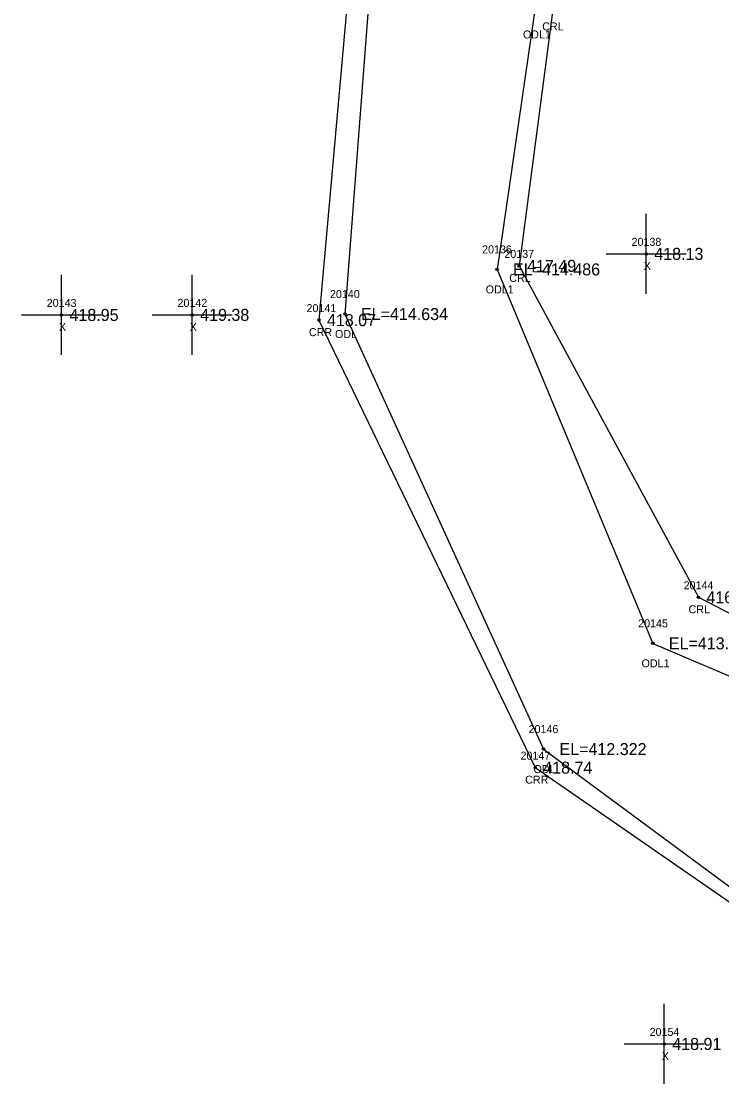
# Model space of a CAD drawing. Extents: x 1613184 to 1614731, y 770859 to 771868.
# Drawn here: x 1613872.1 to 1613959.6, y 771132.5 to 771266.5 of the extents above; entities that cross this region are included whole.
import ezdxf

# ---------------------------------------------------------------- set-up
doc = ezdxf.new("R2010")
doc.units = 0
for name, color, linetype in [('RD_EX_H2O', 7, 'Continuous'), ('RD_EX_H2O_txCode', 7, 'Continuous'), ('RD_EX_Misc', 7, 'Continuous'), ('RD_EX_Misc_txCode', 7, 'Continuous'), ('RD_EX_TX_H2O_ELEV', 7, 'Continuous'), ('RD_EX_TX_Misc_ELEV', 7, 'Continuous'), ('RD_SMD_Locator', 7, 'Continuous')]:
    doc.layers.add(name, color=color, linetype=linetype)

msp = doc.modelspace()

# ---------------------------------------------------------------- linework, layer by layer
at = {"layer": 'RD_EX_H2O'}
for points in [[(1613914.71, 771327.05), (1613912.94, 771270.2), (1613909.29, 771229.14), (1613936.32, 771173.24), (1613961.59, 771155.78), (1613976.99, 771153.11), (1613987.89, 771138.66), (1614016.07, 771061.15), (1614064.07, 770971.34), (1614114.62, 770881.02)], [(1613918.3, 771327.47), (1613915.56, 771269.65), (1613912.54, 771229.9), (1613937.35, 771175.56), (1613962.55, 771156.92), (1613978.15, 771155.33), (1613989.65, 771139.95), (1614019.92, 771062.64), (1614066.64, 770972.38), (1614116.22, 770882.03)], [(1613939.34, 771325.64), (1613936.19, 771267.33), (1613931.54, 771235.48), (1613951.01, 771188.77), (1613971.87, 771179.88), (1613985.53, 771176.18), (1614010.21, 771154.12), (1614036.29, 771069.78), (1614094.78, 770976.9), (1614137.18, 770892.4)], [(1613940.63, 771325.49), (1613938.42, 771267.33), (1613934.3, 771235.92), (1613956.7, 771194.52), (1613973.34, 771185.91), (1613987.6, 771179.19), (1614011.07, 771155.33), (1614038.76, 771071.93), (1614097.41, 770977.46), (1614139.24, 770893.98)]]:
    msp.add_lwpolyline(points, dxfattribs=at)
at = {"layer": 'RD_EX_Misc'}
for p, q in [((1613950.19, 771232.42), (1613950.19, 771242.42)), ((1613945.19, 771237.42), (1613955.19, 771237.42)), ((1613877.12, 771224.79), (1613877.12, 771234.79)), ((1613893.45, 771224.8), (1613893.45, 771234.8)), ((1613872.12, 771229.79), (1613882.12, 771229.79)), ((1613888.45, 771229.8), (1613898.45, 771229.8)), ((1613952.44, 771133.73), (1613952.44, 771143.73)), ((1613947.44, 771138.73), (1613957.44, 771138.73))]:
    msp.add_line(p, q, dxfattribs=at)
at = {"layer": 'RD_SMD_Locator'}
for centre in [(1613950.19, 771237.42), (1613934.3, 771235.92), (1613931.54, 771235.48), (1613877.12, 771229.79), (1613893.45, 771229.8), (1613909.29, 771229.14), (1613912.54, 771229.9), (1613956.7, 771194.52), (1613951.01, 771188.77), (1613937.35, 771175.56), (1613936.32, 771173.24), (1613952.44, 771138.73)]:
    msp.add_circle(centre, 0.15, dxfattribs=at)

# ---------------------------------------------------------------- texts
at = {"layer": 'RD_EX_H2O_txCode'}
for s, p in [('ODL1', (1613934.78, 771264.33)), ('CRL', (1613937.19, 771265.33)), ('20136', (1613929.68, 771237.48)), ('20137', (1613932.46, 771236.92)), ('CRL', (1613933.07, 771233.92)), ('ODL1', (1613930.13, 771232.48)), ('20140', (1613910.67, 771231.9)), ('20141', (1613907.74, 771230.14)), ('CRR', (1613908.04, 771227.14)), ('ODL', (1613911.3, 771226.9)), ('20144', (1613954.86, 771195.52)), ('CRL', (1613955.47, 771192.52)), ('20145', (1613949.18, 771190.77)), ('ODL1', (1613949.6, 771185.77)), ('20146', (1613935.49, 771177.56)), ('20147', (1613934.48, 771174.24)), ('ODL', (1613936.1, 771172.56)), ('CRR', (1613935.06, 771171.24))]:
    msp.add_text(s, height=1, dxfattribs=at).set_placement(p)
at = {"layer": 'RD_EX_Misc_txCode'}
for s, p in [('20138', (1613948.35, 771238.42)), ('X', (1613949.87, 771235.42)), ('20143', (1613875.28, 771230.79)), ('20142', (1613891.62, 771230.8)), ('X', (1613876.8, 771227.79)), ('X', (1613893.14, 771227.8)), ('20154', (1613950.61, 771139.73)), ('X', (1613952.13, 771136.73))]:
    msp.add_text(s, height=1, dxfattribs=at).set_placement(p)
at = {"layer": 'RD_EX_TX_H2O_ELEV'}
for s, p in [('EL=414.486', (1613933.54, 771234.73)), ('417.49', (1613935.3, 771235.17)), ('EL=414.634', (1613914.54, 771229.15)), ('418.07', (1613910.29, 771228.39)), ('416.49', (1613957.7, 771193.77)), ('EL=413.982', (1613953.01, 771188.02)), ('EL=412.322', (1613939.35, 771174.81)), ('418.74', (1613937.32, 771172.49))]:
    msp.add_text(s, height=1.5, dxfattribs=at).set_placement(p)
at = {"layer": 'RD_EX_TX_Misc_ELEV'}
for s, p in [('418.13', (1613951.19, 771236.67)), ('418.95', (1613878.12, 771229.04)), ('419.38', (1613894.45, 771229.05)), ('418.91', (1613953.44, 771137.98))]:
    msp.add_text(s, height=1.5, dxfattribs=at).set_placement(p)

doc.saveas('drawing.dxf')
